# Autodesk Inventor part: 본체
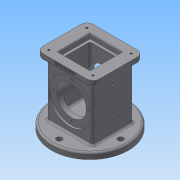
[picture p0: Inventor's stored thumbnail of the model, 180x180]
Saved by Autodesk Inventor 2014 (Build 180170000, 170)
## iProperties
Created: 2018-10
Part Number: 본체
Material: Generic
Document SubType Name: Modeling
Designer: Administrator
Density: 1 g/cm^3
Appearance: Default
Author: Administrator
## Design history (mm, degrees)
sketch "스케치1"
  geometry: L1 (-37, -33)-(37, -33); L2 (37, -33)-(37, 33); L3 (37, 33)-(-37, 33); L4 (-37, 33)-(-37, -33); L5 (-37, -33)-(37, 33); L6 (37, -33)-(-37, 33); 1 further point
  constraints: 12 end point, 2 midpoint, 2 parallel, 1 horizontal, 1 perpendicular
  dimensions: "d0" = 74 distance of L2.end L3.end; "d1" = 66 distance of L1.end L2.end
extrude "돌출1" new body sketch "스케치1" distance "d2" = 88; taper "d3" = 0 deg
sketch "스케치2"
  geometry: C1 r 62.5 at (0, 0); 1 further point
  constraints: 1 centre point, 1 coincident
  dimensions: "d4" = 125 diameter of C1
extrude "돌출2" join sketch "스케치2" distance "d5" = 10; taper "d6" = 0 deg
sketch "스케치3"
  geometry: L1 (-46, -41)-(46, -41); L2 (46, -41)-(46, 41); L3 (46, 41)-(-46, 41); L4 (-46, 41)-(-46, -41); L5 (-46, -41)-(46, 41); L6 (46, -41)-(-46, 41); 1 further point
  constraints: 12 end point, 2 midpoint, 2 parallel, 1 horizontal, 1 perpendicular
  dimensions: "d7" = 92 distance of L2.end L3.end; "d8" = 82 distance of L1.end L2.end
extrude "돌출3" join sketch "스케치3" distance "d9" = 10; taper "d10" = 0 deg
fillet "모깎기1" dims "d11" = 10
sketch "스케치4"
  geometry: L1 (0, 0)-(74, 0) reference; L2 (-25.5, -10)-(99.5, -10) reference; C1 r 35 at (37, 44); 2 further points
  constraints: 1 centre point, 1 midpoint, 1 vertical alignment
  dimensions: "d12" = 70 diameter of C1; "d13" = 54 distance from line of L2 C1.centre
extrude "돌출4" cut sketch "스케치4" distance "d14" = 3; taper "d15" = 0 deg
sketch "스케치5"
  geometry: C1 r 35 at (0, 0) reference; C2 r 24 at (0, 0); 1 further point
  constraints: 1 centre point, 1 coincident
  dimensions: "d16" = 48 diameter of C2
extrude "돌출5" cut sketch "스케치5" stored distance "d17" = 3; taper "d18" = 0 deg
sketch "스케치6" dims "d19" = 58
  geometry: C1 r 24 at (0, 0) reference; C2 r 35 at (0, 0) reference; 3 further points
  constraints: 2 vertical alignment, 1 coincident, 2 other
hole "구멍1" sketch "스케치6" at (0, 29) diameter "d20" = 3.242; stored, may be unused: countersink angle "d24" = 90 deg, drill point angle "d26" = 118 deg; dims "d21" = 4, "d22" = 4, "d23" = 2, "d25" = 6
sketch "스케치7"
  geometry: L1 (-26, -26)-(26, -26); L2 (26, -26)-(26, 26); L3 (26, 26)-(-26, 26); L4 (-26, 26)-(-26, -26); L5 (-26, -26)-(26, 26); L6 (26, -26)-(-26, 26); 1 further point
  constraints: 12 end point, 2 midpoint, 2 parallel, 1 horizontal, 1 perpendicular
  dimensions: "d30" = 52 distance of L2.end L3.end; "d31" = 52 distance of L1.end L2.end
extrude "돌출6" cut sketch "스케치7" distance "d32" = 8; taper "d33" = 0 deg
sketch "스케치8"
  geometry: L1 (-22, -22)-(22, -22); L2 (22, -22)-(22, 22); L3 (22, 22)-(-22, 22); L4 (-22, 22)-(-22, -22); L5 (-22, -22)-(22, 22); L6 (22, -22)-(-22, 22); 1 further point
  constraints: 12 end point, 2 midpoint, 2 parallel, 1 horizontal, 1 perpendicular
  dimensions: "d34" = 44 distance of L2.end L3.end; "d35" = 44 distance of L1.end L2.end
extrude "돌출7" cut sketch "스케치8" distance "d36" = 74; taper "d37" = 0 deg
sketch "스케치9"
  geometry: C1 r 62.5 at (0, 0) reference; C2 r 28 at (0, 0)
  constraints: 1 centre point, 1 coincident
  dimensions: "d38" = 56 diameter of C2
extrude "돌출8" cut sketch "스케치9" distance "d39" = 18; taper "d40" = -10 deg
sketch "스케치10" dims "d41" = 100
  geometry: C1 r 28 at (0, 0) reference; C2 r 62.5 at (0, 0) reference; 2 further points
  constraints: 2 vertical alignment, 1 coincident, 2 other
hole "구멍2" sketch "스케치10" at (0, 50) diameter "d42" = 9; stored, may be unused: countersink angle "d46" = 90 deg, drill point angle "d48" = 118 deg; dims "d43" = 4, "d44" = 4, "d45" = 2, "d47" = 6
hole "구멍3" diameter "d54" = 3.242; stored, may be unused: countersink angle "d58" = 90 deg, drill point angle "d60" = 118 deg; dims "d52" = 10, "d53" = 10, "d55" = 4, "d56" = 4, "d57" = 2, "d59" = 6
hole "구멍4" diameter "d63" = 3.242; stored, may be unused: countersink angle "d67" = 90 deg, drill point angle "d69" = 118 deg; dims "d61" = 10, "d62" = 10, "d64" = 4, "d65" = 4, "d66" = 2, "d68" = 6
hole "구멍5" diameter "d72" = 3.242; stored, may be unused: countersink angle "d76" = 90 deg, drill point angle "d78" = 118 deg; dims "d70" = 10, "d71" = 10, "d73" = 4, "d74" = 4, "d75" = 2, "d77" = 6
hole "구멍6" diameter "d81" = 3.242; stored, may be unused: countersink angle "d85" = 90 deg, drill point angle "d87" = 118 deg; dims "d79" = 10, "d80" = 10, "d82" = 4, "d83" = 4, "d84" = 2, "d86" = 6
fillet "모깎기2" dims "d89" = 3
sketch "스케치12"
  geometry: L1 (72, -7)-(0, -7) reference; L2 (-10, 0)-(-10, -7) reference; 2 further points
  constraints: 1 other
  dimensions: "d90" = 46 distance from line of L2 point (36, -3); "d91" = 4 distance from line of L1 point (36, -3)
feature "엠보싱1" sketch "스케치12" dims "d0" = 74, "d1" = 66, "d92" = 0.5, "d93" = 0
sketch "스케치13"
  geometry: L1 (0, 0)-(66, 0) reference; L2 (0, 0)-(0, 88) reference; L3 (33, 27)-(33, 70); L4 (-29.5, -10)-(95.5, -10) reference; 4 further points
  constraints: 2 coincident, 2 end point, 1 midpoint, 1 parallel, 1 vertical alignment
  dimensions: "d94" = 37 distance from line of L4 L3.start; "d95" = 43 distance of L3.start L3.end
hole "구멍7" sketch "스케치13" at (33, 27), (33, 70) diameter "d96" = 4.134; stored, may be unused: countersink angle "d100" = 90 deg, drill point angle "d102" = 118 deg; dims "d97" = 4, "d98" = 4, "d99" = 2, "d101" = 20
fillet "모깎기3" dims "d103" = 3
fillet "모깎기4" dims "d104" = 3
fillet "모깎기5" dims "d105" = 3
chamfer "모따기1" distance "d106" = 1; stored, may be unused: second distance "d107" = 2, angle "d108" = 45 deg
fillet "모깎기6" dims "d109" = 3
node "솔리드1"
mirror "대칭1"
pattern_circular "원형 패턴1" dims angle "d28" = 360 deg
mirror "대칭2"
pattern_circular "원형 패턴2" dims angle "d50" = 360 deg
